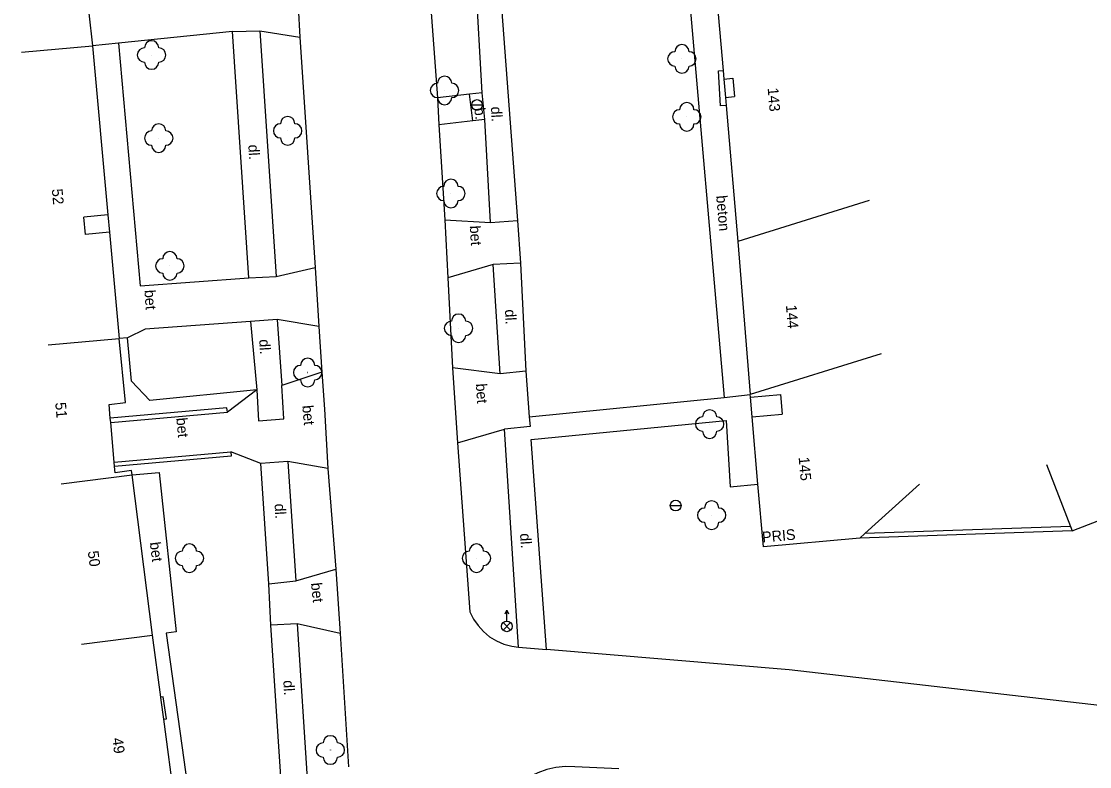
# Model space of a CAD drawing. Extents: x -544674 to -541478, y -1199076 to -1195527.
# Drawn here: x -542650.9 to -542576.1, y -1198570.2 to -1198518 of the extents above; entities that cross this region are included whole.
import ezdxf

# ---------------------------------------------------------------- set-up
doc = ezdxf.new("R2010")
doc.units = 0
for name, color, linetype in [('BUDOVY_MĚŘ', 7, 'Continuous'), ('POMOC_POPIS', 7, 'Continuous'), ('ROZHRANÍ_PLOCH', 7, 'Continuous'), ('ZELEŇ', 7, 'Continuous'), ('ZN_BP', 7, 'Continuous'), ('ZN_DOPLŇKOVÉ', 7, 'Continuous'), ('Č_POPIS_ORIENT', 7, 'Continuous')]:
    doc.layers.add(name, color=color, linetype=linetype)

msp = doc.modelspace()

# ---------------------------------------------------------------- linework, layer by layer
at = {"layer": 'BUDOVY_MĚŘ'}
for points in [[(-542646.97, -1198510.51), (-542645.95, -1198519.69)], [(-542602.45, -1198513.76), (-542601.79, -1198521.41)], [(-542650.93, -1198520.14), (-542645.95, -1198519.69)], [(-542645.95, -1198519.69), (-542644.87, -1198531.53)], [(-542601.79, -1198521.41), (-542601.74, -1198522.01)], [(-542601.74, -1198522.01), (-542601.63, -1198523.3)], [(-542601.63, -1198523.3), (-542601.58, -1198523.86)], [(-542601.58, -1198523.86), (-542600.76, -1198533.39)], [(-542591.57, -1198530.52), (-542600.76, -1198533.39)], [(-542644.87, -1198531.53), (-542644.76, -1198532.73)], [(-542644.76, -1198532.73), (-542644.08, -1198540.18)], [(-542600.76, -1198533.39), (-542599.9, -1198544.12)], [(-542649.06, -1198540.63), (-542644.08, -1198540.18)], [(-542644.7, -1198545.76), (-542644.78, -1198544.81), (-542643.64, -1198544.66), (-542644.08, -1198540.18)], [(-542590.71, -1198541.25), (-542599.9, -1198544.12)], [(-542599.88, -1198544.3), (-542599.9, -1198544.12)], [(-542599.76, -1198545.67), (-542599.88, -1198544.3)], [(-542644.67, -1198546.06), (-542644.7, -1198545.76)], [(-542599.35, -1198550.4), (-542599.76, -1198545.67)], [(-542644.42, -1198548.85), (-542644.67, -1198546.06)], [(-542644.4, -1198549.15), (-542644.42, -1198548.85)], [(-542643.18, -1198549.74), (-542643.22, -1198549.44), (-542644.36, -1198549.59), (-542644.4, -1198549.15)], [(-542579.15, -1198549), (-542577.47, -1198553.36)], [(-542577.35, -1198553.66), (-542566.38, -1198549.42)], [(-542648.14, -1198550.37), (-542643.18, -1198549.74)], [(-542641.75, -1198560.96), (-542643.18, -1198549.74)], [(-542592.22, -1198554.16), (-542598.96, -1198554.77), (-542599.35, -1198550.4)], [(-542588.03, -1198550.4), (-542591.87, -1198553.85)], [(-542591.87, -1198553.85), (-542592.22, -1198554.16)], [(-542577.47, -1198553.36), (-542577.35, -1198553.66)], [(-542646.71, -1198561.59), (-542641.75, -1198560.96)], [(-542641.17, -1198565.31), (-542641.75, -1198560.96)], [(-542640.96, -1198566.85), (-542641.14, -1198565.52), (-542641.17, -1198565.31)], [(-542640.18, -1198572.68), (-542640.96, -1198566.85)]]:
    msp.add_lwpolyline(points, dxfattribs=at)
at = {"layer": 'ROZHRANÍ_PLOCH'}
for points in [[(-542602.45, -1198513.76), (-542604.36, -1198514.03), (-542601.71, -1198544.32)], [(-542631.67, -1198514.76), (-542631.43, -1198519.09)], [(-542618.65, -1198522.98), (-542619.11, -1198515.12)], [(-542617.45, -1198515.01), (-542617.44, -1198515.11), (-542616.19, -1198531.93)], [(-542622.33, -1198516.09), (-542621.79, -1198523.33)], [(-542636.15, -1198518.68), (-542644.12, -1198519.5)], [(-542636.15, -1198518.68), (-542634.24, -1198518.63)], [(-542635.01, -1198535.94), (-542636.15, -1198518.68)], [(-542634.24, -1198518.63), (-542633.09, -1198535.84)], [(-542634.24, -1198518.63), (-542631.43, -1198519.09)], [(-542644.12, -1198519.5), (-542645.95, -1198519.69)], [(-542644.12, -1198519.5), (-542642.62, -1198536.5), (-542635.01, -1198535.94)], [(-542631.43, -1198519.09), (-542630.35, -1198535.21)], [(-542601.58, -1198523.86), (-542601.96, -1198523.89), (-542602.12, -1198521.44), (-542601.79, -1198521.41)], [(-542601.74, -1198522.01), (-542601.1, -1198521.96)], [(-542601.1, -1198521.96), (-542600.99, -1198523.24)], [(-542619.54, -1198523.08), (-542621.79, -1198523.33)], [(-542621.79, -1198523.33), (-542621.69, -1198525.23)], [(-542618.65, -1198522.98), (-542619.54, -1198523.08)], [(-542619.31, -1198524.94), (-542619.54, -1198523.08)], [(-542618.48, -1198524.84), (-542618.65, -1198522.98)], [(-542601.63, -1198523.3), (-542600.99, -1198523.24)], [(-542618.48, -1198524.84), (-542619.31, -1198524.94)], [(-542618.08, -1198532.05), (-542618.48, -1198524.84)], [(-542619.31, -1198524.94), (-542621.69, -1198525.23)], [(-542621.69, -1198525.23), (-542621.28, -1198531.87)], [(-542644.87, -1198531.53), (-542646.56, -1198531.68)], [(-542646.45, -1198532.89), (-542646.56, -1198531.68)], [(-542621.28, -1198531.87), (-542621.07, -1198535.94)], [(-542621.28, -1198531.87), (-542618.08, -1198532.05)], [(-542618.08, -1198532.05), (-542616.19, -1198531.93)], [(-542616.19, -1198531.93), (-542615.97, -1198534.91)], [(-542644.76, -1198532.73), (-542646.45, -1198532.89)], [(-542633.09, -1198535.84), (-542630.35, -1198535.21)], [(-542630.35, -1198535.21), (-542630.1, -1198539.35)], [(-542617.88, -1198535.01), (-542621.07, -1198535.94)], [(-542615.97, -1198534.91), (-542617.88, -1198535.01)], [(-542617.4, -1198542.67), (-542617.88, -1198535.01)], [(-542615.97, -1198534.91), (-542615.6, -1198542.48)], [(-542635.01, -1198535.94), (-542633.09, -1198535.84)], [(-542621.07, -1198535.94), (-542620.73, -1198542.24)], [(-542634.89, -1198538.99), (-542642.26, -1198539.53), (-542643.5, -1198540.15)], [(-542633.01, -1198538.86), (-542634.89, -1198538.99)], [(-542634.89, -1198538.99), (-542634.45, -1198543.77)], [(-542630.1, -1198539.35), (-542633.01, -1198538.86)], [(-542633.01, -1198538.86), (-542632.69, -1198543.48)], [(-542630.1, -1198539.35), (-542629.88, -1198542.54)], [(-542643.5, -1198540.15), (-542644.08, -1198540.18)], [(-542634.45, -1198543.77), (-542641.94, -1198544.54), (-542643.22, -1198543.17), (-542643.5, -1198540.15)], [(-542629.88, -1198542.54), (-542632.69, -1198543.48)], [(-542629.88, -1198542.54), (-542629.71, -1198545.13), (-542629.46, -1198549.3)], [(-542620.73, -1198542.24), (-542620.38, -1198547.49)], [(-542617.4, -1198542.67), (-542620.73, -1198542.24)], [(-542615.6, -1198542.48), (-542617.4, -1198542.67)], [(-542615.6, -1198542.48), (-542615.36, -1198545.68)], [(-542634.45, -1198543.77), (-542634.33, -1198545.95), (-542632.55, -1198545.82), (-542632.69, -1198543.48)], [(-542634.45, -1198543.77), (-542636.5, -1198545.34)], [(-542615.36, -1198545.68), (-542601.71, -1198544.32)], [(-542601.71, -1198544.32), (-542599.9, -1198544.12)], [(-542599.88, -1198544.3), (-542597.76, -1198544.11)], [(-542597.76, -1198544.11), (-542597.64, -1198545.49)], [(-542615.36, -1198545.68), (-542615.3, -1198546.36), (-542617.1, -1198546.53)], [(-542599.76, -1198545.67), (-542597.64, -1198545.49)], [(-542620.38, -1198547.49), (-542617.1, -1198546.53)], [(-542616.11, -1198561.8), (-542617.1, -1198546.53)], [(-542614.15, -1198561.96), (-542615.22, -1198547.27), (-542601.57, -1198545.93), (-542601.29, -1198550.57), (-542599.35, -1198550.4)], [(-542620.38, -1198547.49), (-542619.52, -1198559.33), (-542619.27, -1198559.84), (-542618.95, -1198560.3), (-542618.57, -1198560.72), (-542618.14, -1198561.08), (-542617.65, -1198561.37), (-542617.14, -1198561.59), (-542616.59, -1198561.74), (-542616.11, -1198561.8)], [(-542634.16, -1198548.94), (-542636.26, -1198548.13)], [(-542632.27, -1198548.8), (-542634.16, -1198548.94)], [(-542632.27, -1198548.8), (-542631.72, -1198557.15)], [(-542629.46, -1198549.3), (-542632.27, -1198548.8)], [(-542643.18, -1198549.74), (-542641.29, -1198549.58), (-542640.1, -1198560.74), (-542640.78, -1198560.83), (-542639.15, -1198572.54), (-542640.18, -1198572.68)], [(-542633.61, -1198557.36), (-542634.16, -1198548.94)], [(-542629.46, -1198549.3), (-542628.9, -1198556.35)], [(-542631.72, -1198557.15), (-542628.9, -1198556.35)], [(-542628.9, -1198556.35), (-542628.6, -1198560.84)], [(-542633.61, -1198557.36), (-542631.72, -1198557.15)], [(-542633.47, -1198560.26), (-542633.61, -1198557.36)], [(-542631.62, -1198560.18), (-542633.47, -1198560.26)], [(-542632.72, -1198571.58), (-542633.47, -1198560.26)], [(-542631.62, -1198560.18), (-542630.89, -1198571.38)], [(-542628.6, -1198560.84), (-542631.62, -1198560.18)], [(-542628.6, -1198560.84), (-542628.03, -1198570.18)], [(-542616.11, -1198561.8), (-542614.15, -1198561.96)], [(-542539.33, -1198569.84), (-542574.01, -1198566.06), (-542597.15, -1198563.4), (-542614.15, -1198561.96)], [(-542640.96, -1198566.85), (-542640.76, -1198566.82), (-542641.01, -1198565.29), (-542641.17, -1198565.31)], [(-542609.1, -1198570.34), (-542612.17, -1198570.19), (-542612.83, -1198570.17), (-542613.49, -1198570.24), (-542614.14, -1198570.38), (-542614.76, -1198570.6), (-542615.36, -1198570.89), (-542615.91, -1198571.26), (-542616.42, -1198571.68), (-542616.87, -1198572.17), (-542617.26, -1198572.7), (-542617.58, -1198573.28), (-542617.83, -1198573.89), (-542618, -1198574.53), (-542618.1, -1198575.19), (-542618.11, -1198575.85), (-542618.11, -1198575.94), (-542616.75, -1198593.07), (-542615.84, -1198601.74), (-542615.6, -1198603.63), (-542615.46, -1198604.48)]]:
    msp.add_lwpolyline(points, dxfattribs=at)
at = {"layer": 'ZELEŇ'}
for centre in [(-542641.81, -1198520.33), (-542604.67, -1198520.6), (-542621.29, -1198522.81), (-542604.33, -1198524.66), (-542632.28, -1198525.64), (-542641.31, -1198526.15), (-542620.85, -1198530.03), (-542640.53, -1198535.1), (-542620.31, -1198539.47), (-542630.88, -1198542.57), (-542602.73, -1198546.18), (-542602.59, -1198552.56), (-542639.16, -1198555.58), (-542619.06, -1198555.58), (-542629.29, -1198569.01)]:
    msp.add_circle(centre, 0.0005, dxfattribs=at)
for centre, start, end in [((-542641.81, -1198519.83), 0, 179.99999), ((-542604.67, -1198520.1), 0, 179.99999), ((-542642.31, -1198520.33), 89.99999, 269.99999), ((-542641.31, -1198520.33), 270, 89.99999), ((-542605.17, -1198520.6), 89.99999, 269.99999), ((-542604.17, -1198520.6), 270, 89.99999), ((-542641.81, -1198520.83), 179.99999, 359.99999), ((-542604.67, -1198521.1), 179.99999, 359.99999), ((-542621.29, -1198522.31), 0, 179.99999), ((-542621.79, -1198522.81), 89.99999, 269.99999), ((-542620.79, -1198522.81), 270, 89.99999), ((-542621.29, -1198523.31), 179.99999, 359.99999), ((-542604.83, -1198524.66), 89.99999, 269.99999), ((-542604.33, -1198524.16), 0, 179.99999), ((-542603.83, -1198524.66), 270, 89.99999), ((-542632.28, -1198525.14), 0, 179.99999), ((-542641.81, -1198526.15), 89.99999, 269.99999), ((-542641.31, -1198525.65), 0, 179.99999), ((-542640.81, -1198526.15), 270, 89.99999), ((-542632.78, -1198525.64), 89.99999, 269.99999), ((-542631.78, -1198525.64), 270, 89.99999), ((-542604.33, -1198525.16), 179.99999, 359.99999), ((-542632.28, -1198526.14), 179.99999, 359.99999), ((-542641.31, -1198526.65), 179.99999, 359.99999), ((-542620.85, -1198529.53), 0, 179.99999), ((-542621.35, -1198530.03), 89.99999, 269.99999), ((-542620.35, -1198530.03), 270, 89.99999), ((-542620.85, -1198530.53), 179.99999, 359.99999), ((-542641.03, -1198535.1), 89.99999, 269.99999), ((-542640.53, -1198534.6), 0, 179.99999), ((-542640.03, -1198535.1), 270, 89.99999), ((-542640.53, -1198535.6), 179.99999, 359.99999), ((-542620.81, -1198539.47), 89.99999, 269.99999), ((-542620.31, -1198538.97), 0, 179.99999), ((-542619.81, -1198539.47), 270, 89.99999), ((-542620.31, -1198539.97), 179.99999, 359.99999), ((-542631.38, -1198542.57), 89.99999, 269.99999), ((-542630.88, -1198542.07), 0, 179.99999), ((-542630.38, -1198542.57), 270, 89.99999), ((-542630.88, -1198543.07), 179.99999, 359.99999), ((-542603.23, -1198546.18), 89.99999, 269.99999), ((-542602.73, -1198545.68), 0, 179.99999), ((-542602.23, -1198546.18), 270, 89.99999), ((-542602.73, -1198546.68), 179.99999, 359.99999), ((-542602.59, -1198552.06), 0, 179.99999), ((-542603.09, -1198552.56), 89.99999, 269.99999), ((-542602.09, -1198552.56), 270, 89.99999), ((-542602.59, -1198553.06), 179.99999, 359.99999), ((-542639.16, -1198555.08), 0, 179.99999), ((-542619.06, -1198555.08), 0, 179.99999), ((-542639.66, -1198555.58), 89.99999, 269.99999), ((-542638.66, -1198555.58), 270, 89.99999), ((-542619.56, -1198555.58), 89.99999, 269.99999), ((-542618.56, -1198555.58), 270, 89.99999), ((-542639.16, -1198556.08), 179.99999, 359.99999), ((-542619.06, -1198556.08), 179.99999, 359.99999), ((-542629.29, -1198568.51), 0, 179.99999), ((-542629.79, -1198569.01), 89.99999, 269.99999), ((-542628.79, -1198569.01), 270, 89.99999), ((-542629.29, -1198569.51), 179.99999, 359.99999)]:
    msp.add_arc(centre, 0.5, start, end, dxfattribs=at)
at = {"layer": 'ZN_BP'}
for p, q in [((-542616.93, -1198559.975), (-542616.93, -1198559.225)), ((-542617.195, -1198560.614), (-542616.666, -1198560.086)), ((-542616.666, -1198560.618), (-542617.195, -1198560.086))]:
    msp.add_line(p, q, dxfattribs=at)
msp.add_lwpolyline([(-542617.055, -1198559.475), (-542616.93, -1198559.225), (-542616.805, -1198559.475)], dxfattribs=at)
msp.add_circle((-542616.93, -1198560.35), 0.375, dxfattribs=at)
at = {"layer": 'ZN_DOPLŇKOVÉ'}
for p, q in [((-542619.395, -1198523.83), (-542618.645, -1198523.83)), ((-542605.485, -1198551.89), (-542604.735, -1198551.89))]:
    msp.add_line(p, q, dxfattribs=at)
for points in [[(-542636.5, -1198545.34), (-542636.53, -1198545.04), (-542644.7, -1198545.76)], [(-542644.67, -1198546.06), (-542636.5, -1198545.34)], [(-542644.42, -1198548.85), (-542636.26, -1198548.13)], [(-542636.26, -1198548.13), (-542636.23, -1198548.43), (-542644.4, -1198549.15)], [(-542577.35, -1198553.66), (-542592.22, -1198554.16)], [(-542577.47, -1198553.36), (-542591.87, -1198553.85)]]:
    msp.add_lwpolyline(points, dxfattribs=at)
for centre in [(-542619.02, -1198523.83), (-542605.11, -1198551.89)]:
    msp.add_circle(centre, 0.375, dxfattribs=at)

# ---------------------------------------------------------------- texts
at = {"layer": 'POMOC_POPIS'}
for s, rotation, p in [('b.', 276.92001, (-542619.22, -1198524.06)), ('dl.', 273.17997, (-542618.05, -1198523.96)), ('dl.', 273.37999, (-542635.04, -1198526.62)), ('beton', 274.99997, (-542602.27, -1198530.19)), ('bet', 273.60001, (-542619.53, -1198532.3)), ('bet', 273.60001, (-542642.31, -1198536.8)), ('dl.', 273.58998, (-542617.07, -1198538.17)), ('dl.', 273.37999, (-542634.28, -1198540.26)), ('bet', 273.60001, (-542619.1, -1198543.36)), ('bet', 275.06002, (-542631.26, -1198544.89)), ('bet', 275.06002, (-542640.08, -1198545.76)), ('dl.', 273.37999, (-542633.2, -1198551.77)), ('dl.', 273.71002, (-542616.01, -1198553.85)), ('PRIS', 5.17003, (-542599.02, -1198554.48)), ('bet', 277.26001, (-542641.94, -1198554.48)), ('bet', 275.94003, (-542630.65, -1198557.32)), ('dl.', 273.37999, (-542632.59, -1198564.14))]:
    msp.add_text(s, height=0.75, rotation=rotation, dxfattribs=at).set_placement(p)
at = {"layer": 'Č_POPIS_ORIENT'}
for s, rotation, p in [('143', 274.91999, (-542598.67, -1198522.65)), ('52', 275.21002, (-542648.8, -1198529.73)), ('144', 274.58, (-542597.39, -1198537.85)), ('51', 275.06002, (-542648.56, -1198544.68)), ('145', 275.04002, (-542596.5, -1198548.51)), ('50', 277.26001, (-542646.28, -1198555.1)), ('49', 277.61003, (-542644.57, -1198568.2))]:
    msp.add_text(s, height=0.75, rotation=rotation, dxfattribs=at).set_placement(p)

doc.saveas('drawing.dxf')
